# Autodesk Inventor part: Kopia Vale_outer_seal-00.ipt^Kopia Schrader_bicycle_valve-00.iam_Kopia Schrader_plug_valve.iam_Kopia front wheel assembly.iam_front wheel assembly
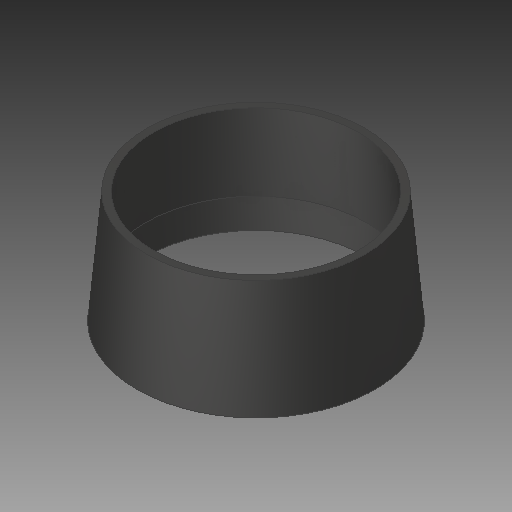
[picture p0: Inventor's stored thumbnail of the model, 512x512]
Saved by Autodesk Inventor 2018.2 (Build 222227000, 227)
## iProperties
Created: 2017-09
Part Number: Kopia Vale_outer_seal-00.ipt^Kopia Schrader_bicycle_valve-00.iam_Kopia Schrader_plug_valve.iam_Kopia front wheel assembly.iam_front wheel assembly
Material: Ogólny
Document SubType Name: Modeling
Designer: Tomasz
Density: 1 g/cm^3
Appearance: Domyślna
Author: Tomasz
Sending System: SolidWorks 2017
Last Author: Tomasz
Last Saved: 2017-09-11
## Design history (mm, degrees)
feature "Vale_outer_seal-00.ipt"
node "Bryła1"
